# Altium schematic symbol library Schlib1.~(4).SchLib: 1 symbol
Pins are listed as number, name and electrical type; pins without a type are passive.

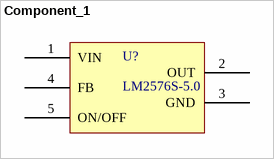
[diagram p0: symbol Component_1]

## Component_1
designator U?, comment LM2576S-5.0
footprint TO263-5A (263，5脚晶体管)
pins: 1 VIN, 2 OUT, 3 GND, 4 FB, 5 ON/OFF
